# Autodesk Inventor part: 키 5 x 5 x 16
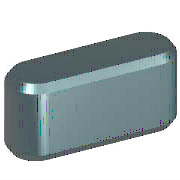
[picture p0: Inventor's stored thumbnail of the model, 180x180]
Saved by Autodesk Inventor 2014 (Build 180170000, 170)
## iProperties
IsCustomPart: 1
Created: 2012-02
Part Number: 키 5 x 5 x 16
Material: 강철, 연강
Description: 키 및 해당 키홈
Document SubType Name: Modeling
Standard: KS B 1311
Designer: mduedu
Standards Organization: KS
Language: ko-KR
Size Designation: 5 x 5 x 16
Categories: <MemberInstance><Categories><Category DisplayName="샤프트 부품" InternalName="7f7aeb1f-a693-4053-b835-cee3144e0d98" Mnemonic="SHFT"><Category DisplayName="키" Interna
Density: 1 g/cm^3
Appearance: 노란색
Author: mduedu
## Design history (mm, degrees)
workplane "Work Plane1"
workplane "Work Plane2"
sketch "스케치1"
  geometry: L1 (2.5, 2.5)-(11.5, 2.5); L2 (11.5, -2.5)-(2.5, -2.5); L3 (0, 8.9)-(0, -4.4) reference; L4 (-3.2, 0)-(19.2, 0) reference; L5 (14, 0)-(14, 7); A1 r 2.5 centre (2.5, 0) between (2.5, 2.5) and (2.5, -2.5); A2 r 2.5 centre (11.5, 0) between (11.5, -2.5) and (11.5, 2.5)
  constraints: 6 end point, 5 point on circle, 4 tangent, 3 point on line, 2 centre point, 1 horizontal, 1 parallel, 1 perpendicular
  dimensions: "d0" = 2.5 radius of A1 (= 0.5 x PB); "d13" = 2.5 radius of A2 (= 0.5 x PB); "d14" = 14 distance between parallel lines of L5 L3 (= NLG)
extrude "본체1" new body sketch "스케치1" taper "d3" = 0 deg; stored distance "d4" = 10
workplane "Work Plane3"
body "Solid1"
chamfer "모따기1" distance "d8" = 0.4 (= PHH); stored, may be unused: second distance "d9" = 0.4 (= PHH), angle "d15" = 45 deg
other parameters: "d1" = -3 (= -PNT), "d2" = 2 (= PH - PNT), "NLG" = 14 [user parameter; used in 3 equation terms], "PB" = 5 [user parameter; used in 2 equation terms], "PNT" = 3 [user parameter; used in 2 equation terms], "PH" = 5 [user parameter; used in 1 equation term], "PHH" = 0.4 [user parameter; used in 2 equation terms], "d10" = 0, "d16" = 0, "d17" = 0, "d18" = 0, "WDMIN" = 12 [user parameter], "PLB2" = 14 (= NLG) [user parameter], "WDMAX" = 17 [user parameter], "PLB1" = 14 (= NLG) [user parameter], "RR" = 0.16 [user parameter], "PUEB" = 2.3 [user parameter]
